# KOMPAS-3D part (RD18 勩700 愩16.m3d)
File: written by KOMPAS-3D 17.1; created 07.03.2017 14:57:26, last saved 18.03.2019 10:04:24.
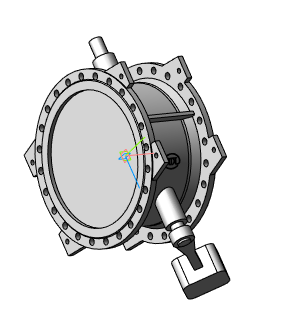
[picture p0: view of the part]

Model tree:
1. Операция без истории:2  (labels: Сталь 20  ГОСТ 1050-88)

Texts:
  RD18 Ду100 Ру16
  RD18 Ду150 Ру16
  RD18 Ду200 Ру16
  RD18 Ду250 Ру16
  RD18 Ду300 Ру16
  RD18 Ду350 Ру16
  RD18 Ду400 Ру10
  RD18 Ду400 Ру16
  RD18 Ду450 Ру10
  RD18 Ду450 Ру16
  RD18 Ду500 Ру10
  RD18 Ду500 Ру16
  RD18 Ду600 Ру10
  RD18 Ду600 Ру16
  RD18 Ду700 Ру10
  RD18 Ду700 Ру16
  RD18 Ду800 Ру10
  RD18 Ду800 Ру16
  RD18 Ду900 Ру10
  RD18 Ду900 Ру16
  RD18 Ду1000 Ру10
  RD18 Ду1000 Ру16
  RD18 Ду1200 Ру16
  RD18 Ду1400 Ру16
